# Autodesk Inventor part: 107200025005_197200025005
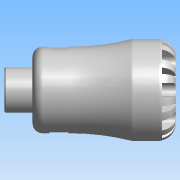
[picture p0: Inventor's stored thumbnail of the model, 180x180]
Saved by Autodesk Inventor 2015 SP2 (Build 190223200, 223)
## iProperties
Created: 2016-12
Part Number: 107200025005_197200025005
Material: PVC-Piping
Description: PLASSON MALE INTEGRAL BRASS THREAD 25X1/2" SERIES 1
Document SubType Name: Modeling
Designer: KIM
Mass: 61.7504 g
Surface Area: 140.097 cm^2
Volume: 44.1074 cm^3
Density: 1.4 g/cm^3
Appearance: Smooth - White
Author: KIM
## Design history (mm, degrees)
derived "1072.ipt"
feature "Solid1::1072.ipt"
tag "TaggingFeature1"
body "Solid1"
other parameters: "d0" = 79, "d1" = 20.16, "d2" = 25, "d3" = 31.25, "d4" = 47, "d6" = 48, "d8" = 39.95, "d13" = 6.3, "d14" = 6.3, "d15" = 0, "d17" = 360 deg, "d19" = 8 deg, "d20" = 0.5, "d21" = 0.5, "d22" = 8 deg, "d24" = 0, "d26" = 360 deg, "d32" = 4.7, "d33" = 4.7, "d34" = 20.955, "d38" = 13, "d39" = 0.62865, "d42" = 8.75, "d43" = 5.75, "d45" = 12.348, "d46" = 0, "d59" = 360 deg, "d61" = 7.4375, "d62" = 0.5, "d64" = 0, "d65" = 0.47, "d68" = 3.57143, "d_" = 25, "E_" = 47, "H_" = 79, "l_" = 48, "R_" = 20.955, "l_2" = 13, "d9" = 7.875, "d11" = 47, "d12" = 31.25
